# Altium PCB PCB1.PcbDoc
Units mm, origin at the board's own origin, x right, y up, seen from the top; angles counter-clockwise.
Board outline 23 x 11.4 mm, 2 copper layers (Top Layer, Bottom Layer); 16 components, 9 nets, 45 pads, 0 vias.
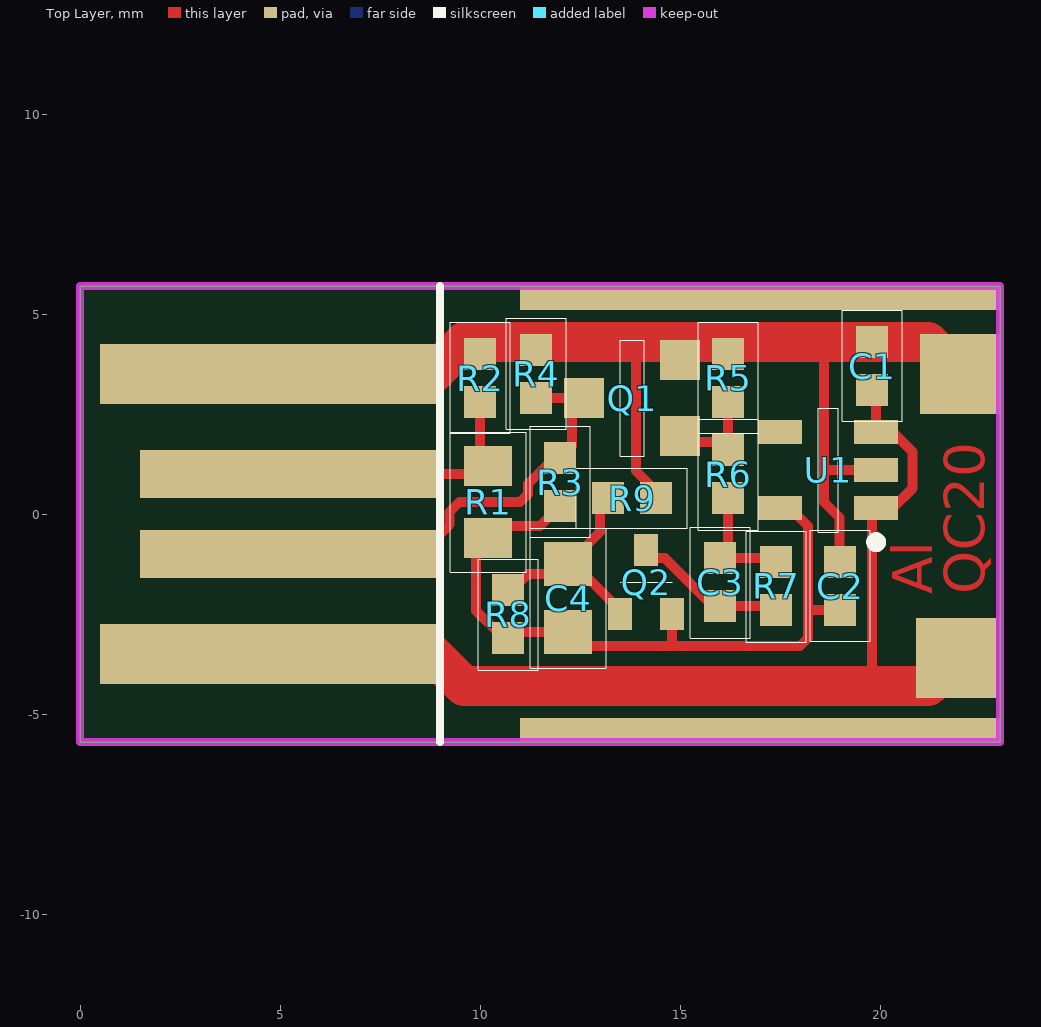
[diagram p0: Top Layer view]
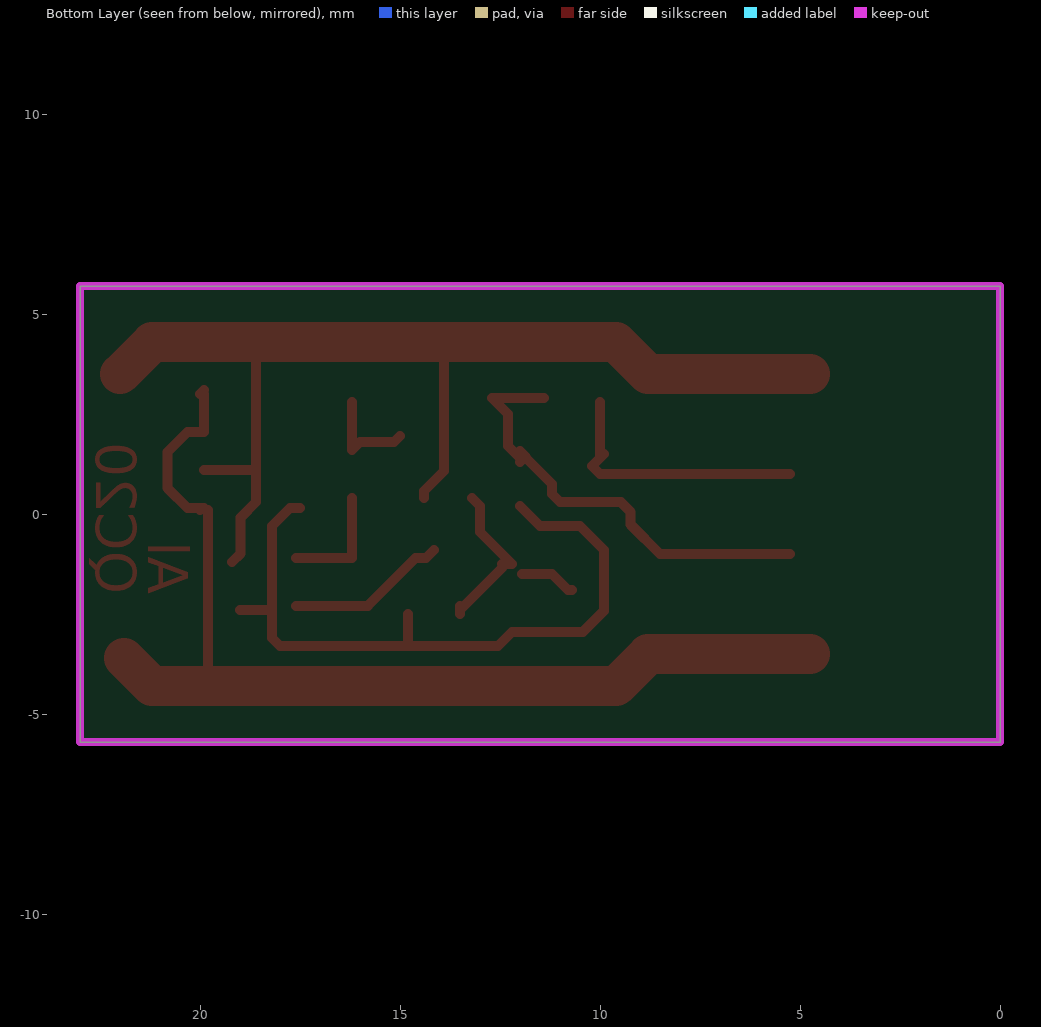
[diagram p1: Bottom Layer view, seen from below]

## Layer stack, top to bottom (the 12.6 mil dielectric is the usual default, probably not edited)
Top Solder: solder mask 0.0102, Solder Resist, Dk 3.5
Top Layer: signal copper 0.0356
Dielectric 1: dielectric 0.32, FR-4, Dk 4.8
Bottom Layer: signal copper 0.0356
Bottom Solder: solder mask 0.0102, Solder Resist, Dk 3.5

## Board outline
0,-5.7 0,5.7 23,5.7 23,-5.7

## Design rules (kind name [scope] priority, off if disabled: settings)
Clearance Clearance_keep_out [All vs OnLayer('Keep-Out Layer')] p1: gap=0 ignorepadtopadclearanceinfootprint=FALSE
Clearance [All] p2: gap=0.24 ignorepadtopadclearanceinfootprint=FALSE
HoleSize [All] p1: absolutevalues=TRUE maxlimit=3 minlimit=0.6 maxpercent=80.000 minpercent=20.000
MinimumAnnularRing [All] p1: minimumring=0.3
MinimumSolderMaskSliver [All] p1: minsoldermaskwidth=0.15
PolygonConnect [All] p1: connectstyle=Relief reliefconductorwidth=0.254 reliefentries=4 polygonreliefangle="90 Angle" airgapwidth=0.254
RoomDefinition Sheet1 [InComponentClass('Sheet1')] p1: confinementstyle=ConfineIn formatcopy=TRUE lockcomponents=FALSE outline -23.7,-17.8 72.9,-17.8 72.9,15.2 -23.7,15.2
RoutingVias [All] p1: holewidth=0.711 width=1.27 viastyle="Through Hole" minholewidth=0.711 minwidth=1.27 maxholewidth=0.711 maxwidth=1.27
SilkToSilkClearance [All] p1: silktosilkclearance=0.01
SilkToSolderMaskClearance [IsPad] p1: minsilkscreentomaskgap=0.15 clearancetoexposedcopper=TRUE
SolderMaskExpansion [All] p1: expansion=0.102
Width [All] p1: maxlimit=1 minlimit=0.2 preferedwidth=0.3
26 further rules are at their usual default settings.

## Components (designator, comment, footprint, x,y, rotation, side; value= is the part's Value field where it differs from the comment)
C1 "0.1uF" CAP-0402 19.8,3.7 r270 top
C2 "0.1uF" CAP-0402 19,-1.8 r270 top
C3 "1uF" CAP-0402 16,-1.7 r90 top
C4 "4.7uF" CAP-0603 12.2,-2.1 r90 top
Q1 "IRLML2402" SOT-23 15,1.95 r90 top
Q2 "BC857BW" SOT-323 13.5,-2.5 r0 top
R1 "10K" RES-0603 10.2,0.3 r270 top value=1K
R2 "2.2K" RES-0402 10,3.4 r270 top value=1K
R3 "10K" RES-0402 12,0.8 r270 top value=1K
R4 "2.2K" RES-0402 11.4,3.5 r270 top value=1K
R5 "220K" RES-0402 16.2,3.4 r270 top value=1K
R6 "47K" RES-0402 16.2,1 r90 top value=1K
R7 "2M" RES-0402 17.4,-1.8 r90 top value=1K
R8 "2M" RES-0402 10.7,-2.5 r90 top value=1K
R9 "2M" RES-0402 13.8,0.4 r0 top value=1K
U1 "LP2980AIM5-3.3" TI-DBV5_N 18.7,1.1 r180 top

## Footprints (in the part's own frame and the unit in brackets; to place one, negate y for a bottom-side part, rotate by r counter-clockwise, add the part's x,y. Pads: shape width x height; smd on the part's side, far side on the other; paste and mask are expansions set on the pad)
CAP-0402 [mm]
  rect 0.8x0.8 smd: 1(-0.6,0) 2(0.6,0)
  silkscreen extent -1.4,-0.75 1.38,0.75, body extent -0.5,-0.25 0.5,0.25, height 0.55
CAP-0603 [mm]
  rect 1.1x1.2 smd: 1(-0.85,0) 2(0.85,0)
  silkscreen extent -1.75,-0.95 1.75,0.95, body extent -0.85,-0.4 0.75,0.4, height 0.9
RES-0402 [mm]
  rect 0.8x0.8 smd: 1(-0.6,0) 2(0.6,0)
  silkscreen extent -1.4,-0.75 1.38,0.75, body extent -0.5,-0.25 0.5,0.25, height 0.35
RES-0603 [mm]
  rect 1x1.2 smd: 1(-0.9,0) 2(0.9,0)
  silkscreen extent -1.75,-0.95 1.75,0.95, body extent -0.85,-0.4 0.75,0.4, height 0.45
SOT-23 [mm]
  rect 1x1 smd: 1(0,0) 2(1.9,0) 3(0.95,2.4)
  silkscreen extent -0.5,0.9 2.4,1.5, body extent -0.45,0.55 2.45,1.85, height 1
SOT-323 [mm]
  rect 0.6x0.8 smd: 1(0,0) 2(1.3,0) 3(0.65,1.6)
  silkscreen extent 0,0.8 1.3,0.8, body extent -0.4,0.2 1.6,1.4, height 0.9
TI-DBV5_N [mm] "SOT23, 5-Leads, Body 2.9x1.6mm, Pitch 0.95mm, IPC Medium Density"
  rect 1.1x0.6 smd: 1(-1.2,0.95) 2(-1.2,0) 3(-1.2,-0.95) 4(1.2,-0.95) 5(1.2,0.95)
  silkscreen extent -1.33,-1.55 0.25,1.92, body extent -0.87,-1.52 0.87,1.53, height 1.45

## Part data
C1 C2 C3 C4: library part Cap, "Capacitor", Voltage=16V
Q1: "HEXFET Power MOSFET"
Q2: library part BC857B, "PNP General Purpose Amplifier"
R1 R2 R3 R4 R5 R6 R7 R8 R9: library part Res2, "Resistor"
U1: library part TPS79333DBVR, "Single Output High PSRR LDO, 200 mA, Fixed 3.3 V Output, 2.7 to 5.5 V Input, 5-pin SOT-23 (DBV), -40 to 85 degC, Green (RoHS & no Sb/Br)", Manufacturer="Texas Instruments", Rating=Catalog, Supplier Part Number 1=296-12961-2-ND

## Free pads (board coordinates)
  rect 8.5x1.5 smd: 1(4.75,-3.5) 4(4.75,3.5)
  rect 7.5x1.2 smd: 2(5.25,-1) 3(5.25,1)
  rect 12x0.6 smd: 14(17,5.4) 15(17,-5.4)
  rect 2x2 smd: 16(22,3.5) 17(21.9,-3.6)

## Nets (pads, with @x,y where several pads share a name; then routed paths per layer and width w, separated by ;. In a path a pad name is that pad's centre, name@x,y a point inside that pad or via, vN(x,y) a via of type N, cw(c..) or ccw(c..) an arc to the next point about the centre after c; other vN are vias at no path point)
D+: pad.3 R1.1 R2.2 | length 6.9
  Top Layer w0.25: pad.3 10,1 R1.1 R1.1@10,1.4 ; R1.1@9.9,1.5 R1.1@10,1.4 ; R2.2 R1.1@10,1.4
D-: pad.2 Q1.3 R3.1 R4.2 | length 11.6
  Top Layer w0.25: pad.2 8.5,-1 9.235,-0.265 9.235,0.051 9.484,0.3 11,0.3 11.2,0.5 11.2,0.75 11.85,1.4 R3.1@11.9,1.4 ; R4.2 12.7,2.9 12.3,2.5 12.3,1.7 R3.1 R3.1@11.9,1.4 ; R3.1@12,1.3 11.95,1.35 R3.1@11.9,1.4 ; R3.1@12,1.575 11.862,1.437 R3.1@11.9,1.4
GND: C1.1 C2.1 pad.4 pad.16 Q1.2 R2.1 R4.1 R5.1 R9.2 U1.2 | length 29.1
  Top Layer w0.25: 13.9,4.3 13.9,1.081 14.4,0.581 R9.2 ; 18.6,4.3 18.6,1.1 ; C2.1@19.2,-1.2 18.985,-0.985 18.985,-0.085 18.6,0.3 18.6,1.1 ; U1.2 18.6,1.1
  Top Layer w1: pad.4 8.8,3.5 9.6,4.3 13.9,4.3 18.6,4.3 21.2,4.3 pad.16
NetC3_1: C3.1 Q2.3 R7.1 | length 4
  Top Layer w0.25: Q2.3 14.35,-1.1 14.616,-1.1 C3.1@15.816,-2.3 ; C3.1@15.8,-2.3 C3.1@15.816,-2.3 ; R7.1@17.6,-2.3 16.2,-2.3 C3.1 C3.1@15.816,-2.3
NetC3_2: C3.2 R6.1 R7.2 | length 2.9
  Top Layer w0.25: R6.1 16.2,-1.1 R7.2@17.6,-1.1
NetC4_2: C4.2 Q2.1 R8.2 R9.1 | length 5.4
  Top Layer w0.25: R8.2 10.8,-1.9 11.2,-1.5 C4.2@11.95,-1.5 ; C4.2@12.45,-1.35 Q2.1@13.5,-2.4 ; C4.2@12.45,-1.25 C4.2 13,-0.45 13,0.2 R9.1 ; Q2.1 Q2.1@13.5,-2.4 ; Q2.1@13.5,-2.3 Q2.1@13.5,-2.4
NetQ1_1: Q1.1 R5.2 R6.2 | length 2.5
  Top Layer w0.25: Q1.1 15.15,1.8 16,1.8 R6.2 R5.2
VDD: C2.2 C4.1 Q2.2 R1.2 R3.2 R8.1 U1.5 | length 18.1
  Top Layer w0.25: R3.2 11.5,-0.3 10.5,-0.3 R1.2 9.9,-0.9 9.9,-2.416 10.434,-2.95 C4.1 12.55,-3.3 14.8,-3.3 ; Q2.2 14.8,-3.3 ; U1.5 17.75,0.15 18.2,-0.3 18.2,-3.1 18,-3.3 14.8,-3.3 ; 18.2,-2.4 18.4,-2.4 C2.2
Vin: C1.2 pad.1 pad.17 U1.1 U1.3 | length 26.5
  Top Layer w0.25: 19.8,-4.2 U1.1@19.8,0.1 ; U1.1 U1.1@19.95,0.15 ; C1.2@19.9,3 U1.3 20.316,2.05 20.815,1.551 20.815,0.649 20.316,0.15 U1.1@19.95,0.15 ; C1.2@19.9,3.1 C1.2@20,3 ; 20,-4.3 20.1,-4.2 ; U1.1@20,0.1 U1.1@19.95,0.15
  Top Layer w1: pad.1 8.8,-3.5 9.6,-4.3 20,-4.3 21.2,-4.3 pad.17
pads on no net: U1.4

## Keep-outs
Keep-Out Layer:
  the board outline again, w0.2

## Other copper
Top Layer:
  text "Al" at 21.3,-2 h1 r90
  text "QC20" at 22.6,-2 h1 r90

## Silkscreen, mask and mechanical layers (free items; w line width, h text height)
Top Overlay:
  lines w0.2: 9,-5.7 9,5.7
Top Text:
  lines w0.1: 12.8,3.7 12.8,5.9 ; 14.7,-4.2 14.7,-3 ; 14.8,2 15,2.2 15,1.7 ; 18,5.9 18,2.8 18.1,2.7 ; 19.8,0.3 19.9,0.4 19.9,0
  text "GND" at 6,3.2 h0.7
  text "GND" at 20.9,3 h0.7
  text "D+" at 6,0.6 h0.7
  text "D-" at 6,-1.3 h0.7
  text "VDD" at 6,-3.9 h0.7
  text "VDD" at 20.8,-4 h0.7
